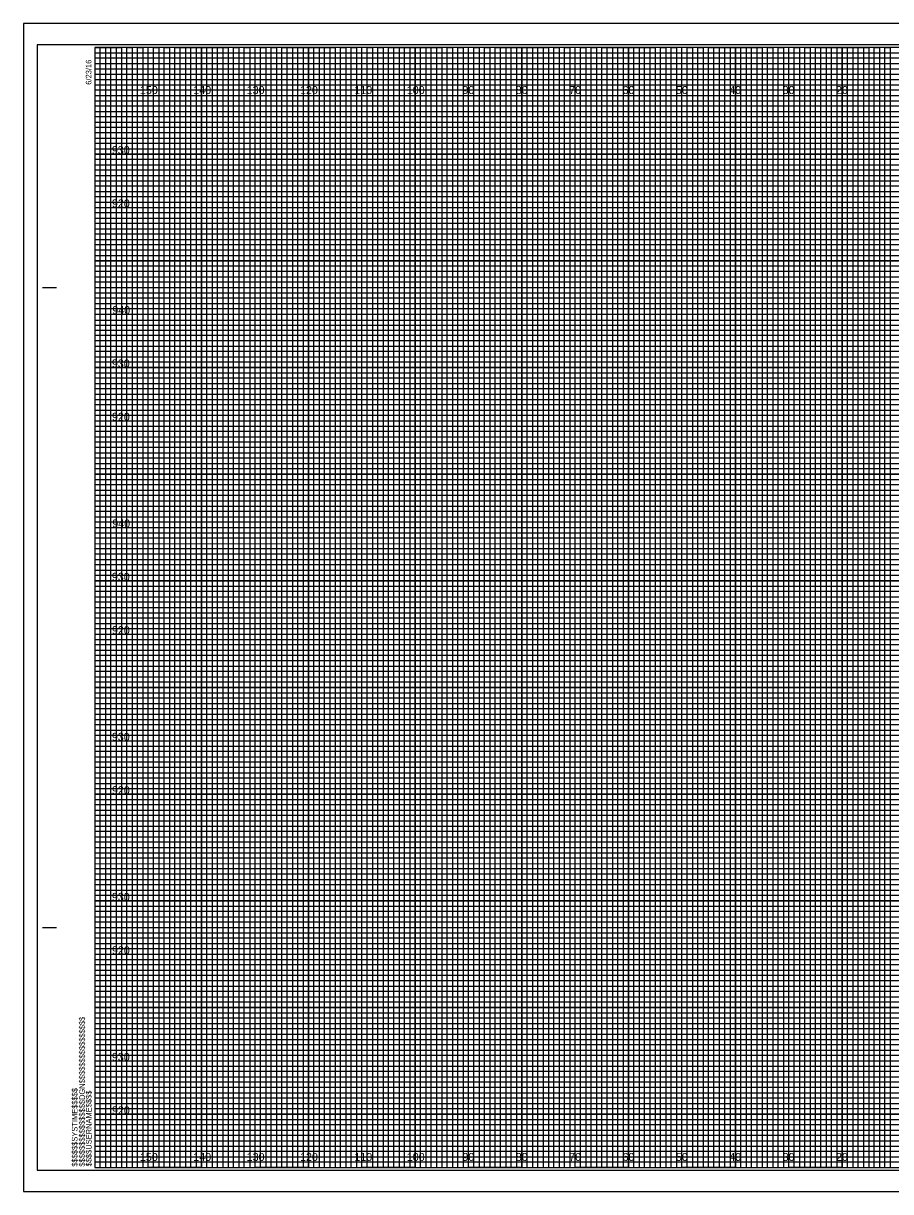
# Model space of a CAD drawing. Extents: x -13 to 323, y 216 to 434.
# Drawn here: x -13.4 to 149.1, y 215.5 to 434.5 of the extents above; entities that cross this region are included whole.
import ezdxf

# ---------------------------------------------------------------- set-up
doc = ezdxf.new("R2010")
doc.units = 0
for name, color, linetype in [('Prop XS Elevation Labels', 7, 'Continuous'), ('Prop XS Label Text', 7, 'Continuous'), ('Prop XS Shear Point Element', 7, 'Continuous'), ('Prop XS Shear Point Label', 7, 'Continuous'), ('Scratch_Level_1', 7, 'Continuous'), ('Scratch_Level_4', 7, 'Continuous'), ('Sheet Cross Section Grid Minor 2 CELL', 7, 'Continuous'), ('Sheet Cutting Line CELL', 7, 'Continuous'), ('Sheet DOT Grid CELL', 7, 'Continuous'), ('Sheet Plot Border Inside CELL', 7, 'Continuous'), ('Sheet Plot Border Outside CELL', 7, 'Continuous')]:
    doc.layers.add(name, color=color, linetype=linetype)

msp = doc.modelspace()

# ---------------------------------------------------------------- linework, layer by layer
at = {"layer": 'Prop XS Label Text'}
for points in [[(0, 430), (5, 430), (5, 220), (15, 220), (15, 430), (25, 430), (25, 220), (35, 220), (35, 430), (45, 430), (45, 220), (55, 220), (55, 430), (65, 430), (65, 220), (75, 220), (75, 430), (85, 430), (85, 220), (95, 220), (95, 430), (105, 430), (105, 220), (115, 220), (115, 430), (125, 430), (125, 220), (135, 220), (135, 430), (145, 430), (145, 220), (155, 220)], [(0, 425), (275, 425)], [(0, 405), (320, 405), (320, 415), (0, 415)], [(0, 385), (320, 385), (320, 395), (0, 395)], [(0, 365), (320, 365), (320, 375), (0, 375)], [(0, 345), (320, 345), (320, 355), (0, 355)], [(0, 325), (320, 325), (320, 335), (0, 335)], [(0, 305), (320, 305), (320, 315), (0, 315)], [(0, 285), (320, 285), (320, 295), (0, 295)], [(0, 265), (320, 265), (320, 275), (0, 275)], [(0, 245), (320, 245), (320, 255), (0, 255)], [(0, 225), (320, 225), (320, 235), (0, 235)]]:
    msp.add_lwpolyline(points, dxfattribs=at)
at = {"layer": 'Prop XS Shear Point Element'}
for p, q in [((-9.8, 385), (-7.3, 385)), ((-9.7, 385), (-7.2, 385)), ((-9.8, 265), (-7.3, 265)), ((-9.7, 265), (-7.2, 265)), ((0, 220), (0, 220)), ((0, 220), (0, 220)), ((0, 220), (0, 220)), ((0, 220), (0, 220)), ((0, 220), (0, 220)), ((0, 220), (0, 220)), ((0, 220), (0, 220))]:
    msp.add_line(p, q, dxfattribs=at)
msp.add_lwpolyline([(320, 430), (0, 430), (0, 220), (320, 220)], close=True, dxfattribs=at)
at = {"layer": 'Prop XS Shear Point Label'}
for p, q in [((0, 429), (260, 429)), ((260, 427.98), (0, 427.98)), ((0, 427.98), (0, 427)), ((0, 427), (260, 427)), ((260, 425.89), (0, 425.89)), ((0, 425.89), (0, 424)), ((0, 424), (320, 424))]:
    msp.add_line(p, q, dxfattribs=at)
for points in [[(0, 423), (270, 423), (320, 423), (320, 422), (0, 422)], [(0, 421), (320, 421), (320, 419), (0, 419)], [(0, 418), (320, 418), (320, 417), (0, 416.98)], [(0, 416), (320, 416), (320, 414), (0, 414)], [(0, 413), (320, 413), (320, 412), (0, 412)], [(0, 411), (320, 411), (320, 409), (0, 409)], [(0, 408), (320, 408), (320, 407), (0, 407)], [(0, 406), (320, 406), (320, 404), (0, 404)], [(0, 403), (320, 403), (320, 402), (0, 402)], [(0, 401), (320, 401), (320, 399), (0, 399)], [(0, 398), (320, 398), (320, 397), (0, 397)], [(0, 396), (320, 396), (320, 393.95), (320, 393), (320, 392), (0, 392)], [(0, 394), (320, 394), (320, 393), (0, 393)], [(0, 391), (320, 391), (320, 389), (0, 389.03)], [(0, 389.03), (320, 389), (320, 388), (0, 388)], [(0, 387), (320, 387), (320, 386), (0, 386)], [(0, 384), (320, 384), (320, 383), (0, 383)], [(0, 382), (320, 382), (320, 381), (0, 381)], [(-0.07, 378.89), (320, 378.89), (320, 377.88), (-0.07, 377.88)], [(0, 377), (320, 377), (320, 376), (0, 376)], [(0, 374), (320, 374), (320, 373), (0, 373)], [(0, 372), (320, 372), (320, 371), (0, 371)], [(0, 369), (320, 369), (320, 368), (0, 368)], [(0, 367), (320, 367), (320, 366), (0, 366)], [(0, 364), (320, 364), (320, 363), (0, 363)], [(0, 362), (320, 362), (320, 361), (0, 361)], [(0, 359), (320, 359), (319.99, 357.98), (0, 358)], [(0, 357), (320, 357), (320, 356), (0, 356)], [(0, 354), (320, 354), (320, 353), (0, 353)], [(0, 352), (320, 352), (320, 351), (0, 351)], [(0, 349), (320, 349), (320, 348), (0, 348)], [(0, 347), (320, 347), (320, 346), (0, 346)], [(0, 344), (320, 344), (320, 343), (0, 343)], [(0, 342), (320, 342), (320, 341), (0, 341)], [(0, 339), (320, 339), (320, 338), (0, 338)], [(0, 336.99), (320.07, 336.91), (320, 336), (0, 336)], [(0, 334), (320, 334), (320, 333), (0, 333)], [(0, 332), (320, 332), (320, 331), (0, 331)], [(0, 329), (320, 329), (320, 328), (0, 328)], [(0, 327), (320, 327), (320, 326), (0, 326)], [(0, 324), (320, 324), (320, 323), (0, 323)], [(0, 322), (320, 322), (320, 321), (0, 321)], [(0, 319), (320, 319), (320, 318), (0, 318)], [(0, 317), (320, 317), (320, 316), (0, 316)], [(0, 314), (320, 314), (320, 313), (0, 313)], [(0, 312), (320, 312), (320, 311), (0, 311)], [(0, 309), (320, 309), (320, 308), (0, 308)], [(0, 307), (320, 307), (320, 306), (0, 306)], [(0, 304), (320, 304), (320, 303), (0, 303)], [(0, 302), (320, 302), (320, 301), (0, 301)], [(0, 299), (320, 299), (319.99, 297.98), (0, 298)], [(0, 297), (320, 297), (320, 296), (0, 296)], [(0, 294), (320, 294), (320, 293), (0, 293)], [(0, 292), (320, 292), (320, 291), (0, 291)], [(0, 289), (320, 289), (320, 288), (0, 288)], [(0, 287), (320, 287), (320, 286), (0, 286)], [(0, 284), (320, 284), (320, 283), (0, 283)], [(0, 282), (320, 282), (320, 281), (0, 281)], [(0, 279), (320, 279), (320, 278), (0, 278)], [(0, 276.99), (320.07, 276.91), (320, 276), (0, 276)], [(0, 274), (320, 274), (320, 273), (0, 273)], [(0, 272), (320, 272), (320, 271), (0, 271)], [(0, 269), (320, 269), (320, 268), (0, 268)], [(0, 267), (320, 267), (320, 266), (0, 266)], [(0, 264), (320, 264), (320, 263), (0, 263)], [(0, 262), (320, 262), (320, 261), (0, 261)], [(0, 259), (320, 259), (320, 258), (0, 258)], [(0, 257), (320, 257), (320, 256), (0, 256)], [(0, 254), (320, 254), (320, 253), (0, 253)], [(0, 252), (320, 252), (320, 251), (0, 251)], [(0, 249), (320, 249), (320, 248), (0, 248)], [(0, 247), (320, 247), (320, 246), (0, 246)], [(0, 244), (320, 244), (320, 243), (0, 243)], [(0, 242), (320, 242), (320, 241), (0, 241)], [(0, 239), (320, 239), (320, 238), (0, 238)], [(0, 237), (320, 237), (320, 236), (0, 236)], [(0, 234), (320, 234), (320, 233), (0, 233)], [(0, 232), (320, 232), (320, 231), (0, 231)], [(0, 229), (320, 229), (320, 228), (0, 228)], [(0, 227), (320, 227), (320, 226), (0, 226)], [(0, 224), (320, 224), (320, 223), (0, 223)], [(0, 222), (320, 222), (320, 221), (0, 221)]]:
    msp.add_lwpolyline(points, dxfattribs=at)
at = {"layer": 'Scratch_Level_4'}
for p, q in [((10, 430), (0, 430)), ((10, 220), (10, 430)), ((30, 430), (20, 430)), ((20, 430), (20, 220)), ((30, 220), (30, 430)), ((50, 430), (40, 430)), ((40, 430), (40, 220)), ((50, 220), (50, 430)), ((70, 430), (60, 430)), ((60, 430), (60, 220)), ((70, 220), (70, 430)), ((90, 430), (80, 430)), ((80, 430), (80, 220)), ((90, 220), (90, 430)), ((110, 430), (100, 430)), ((100, 430), (100, 220)), ((110, 220), (110, 430)), ((130, 430), (120, 430)), ((120, 430), (120, 220)), ((130, 220), (130, 430)), ((150, 430), (140, 430)), ((140, 430), (140, 220)), ((20, 220), (10, 220)), ((40, 220), (30, 220)), ((60, 220), (50, 220)), ((80, 220), (70, 220)), ((100, 220), (90, 220)), ((120, 220), (110, 220)), ((140, 220), (130, 220))]:
    msp.add_line(p, q, dxfattribs=at)
for points in [[(0, 420), (320, 420), (320, 410), (0, 410)], [(0, 400), (320, 400), (320, 390), (0, 390)], [(0, 380), (320, 380), (320, 370), (0, 370)], [(0, 360), (320, 360), (320, 350), (0, 350)], [(0, 340), (320, 340), (320, 330), (0, 330)], [(0, 320), (320, 320), (320, 310), (0, 310)], [(0, 300), (320, 300), (320, 290), (0, 290)], [(0, 280), (320, 280), (320, 270), (0, 270)], [(0, 260), (320, 260), (320, 250), (0, 250)], [(0, 240), (320, 240), (320, 230), (0, 230)]]:
    msp.add_lwpolyline(points, dxfattribs=at)
at = {"layer": 'Sheet Cross Section Grid Minor 2 CELL'}
for points in [[(0, 220), (1, 220), (1, 430), (2, 430), (2, 220)], [(2, 220), (3, 220), (3, 430), (4, 430), (4, 220)], [(5, 220), (6, 220), (6, 430), (7, 430), (7, 220)], [(7, 220), (8, 220), (8, 430), (9, 430), (9, 220)], [(10, 220), (11, 220), (11, 430), (12, 430), (12, 220)], [(12, 220), (13, 220), (13, 430), (14, 430), (14, 220)], [(15, 220), (16, 220), (16, 430), (17, 430), (17, 220)], [(17, 220), (18, 220), (18, 430), (19, 430), (19, 220)], [(20, 220), (21, 220), (21, 430), (22, 430), (22, 220)], [(22, 220), (23, 220), (23, 430), (24, 430), (24, 220)], [(25, 220), (26, 220), (26, 430), (27, 430), (27, 220)], [(27, 220), (28, 220), (28, 430), (29, 430), (29, 220)], [(30, 220), (31, 220), (31, 430), (32, 430), (32, 220)], [(32, 220), (33, 220), (33, 430), (34, 430), (34, 220)], [(35, 220), (36, 220), (36, 430), (37, 430), (37, 220)], [(37, 220), (38, 220), (38, 430), (39, 430), (39, 220)], [(40, 220), (41, 220), (41, 430), (42, 430), (42, 220)], [(42, 220), (43, 220), (43, 430), (44, 430), (44, 220)], [(45, 220), (46, 220), (46, 430), (47, 430), (47, 220)], [(47, 220), (48, 220), (48, 430), (49, 430), (49, 220)], [(50, 220), (51, 220), (51, 430), (52, 430), (52, 220)], [(52, 220), (53, 220), (53, 430), (54, 430), (54, 220)], [(55, 220), (56, 220), (56, 430), (57, 430), (57, 220)], [(57, 220), (58, 220), (58, 430), (59, 430), (59, 220)], [(60, 220), (61, 220), (61, 430), (62, 430), (62, 220)], [(62, 220), (63, 220), (63, 430), (64, 430), (64, 220)], [(65, 220), (66, 220), (66, 430), (67, 430), (67, 220)], [(67, 220), (68, 220), (68, 430), (69, 430), (69, 220)], [(70, 220), (71, 220), (71, 430), (72, 430), (72, 220)], [(72, 220), (73, 220), (73, 430), (74, 430), (74, 220)], [(75, 220), (76, 220), (76, 430), (77, 430), (77, 220)], [(77, 220), (78, 220), (78, 430), (79, 430), (79, 220)], [(80, 220), (81, 220), (81, 430), (82, 430), (82, 220)], [(82, 220), (83, 220), (83, 430), (84, 430), (84, 220)], [(85, 220), (86, 220), (86, 430), (87, 430), (87, 220)], [(87, 220), (88, 220), (88, 430), (89, 430), (89, 220)], [(90, 220), (91, 220), (91, 430), (92, 430), (92, 220)], [(92, 220), (93, 220), (93, 430), (94, 430), (94, 220)], [(95, 220), (96, 220), (96, 430), (97, 430), (97, 220)], [(97, 220), (98, 220), (98, 430), (99, 430), (99, 220)], [(100, 220), (101, 220), (101, 430), (102, 430), (102, 220)], [(102, 220), (103, 220), (103, 430), (104, 430), (104, 220)], [(105, 220), (106, 220), (106, 430), (107, 430), (107, 220)], [(107, 220), (108, 220), (108, 430), (109, 430), (109, 220)], [(110, 220), (111, 220), (111, 430), (112, 430), (112, 220)], [(112, 220), (113, 220), (113, 430), (114, 430), (114, 220)], [(115, 220), (116, 220), (116, 430), (117, 430), (117, 220)], [(117, 220), (118, 220), (118, 430), (119, 430), (119, 220)], [(120, 220), (121, 220), (121, 430), (122, 430), (122, 220)], [(122, 220), (123, 220), (123, 430), (124, 430), (124, 220)], [(125, 220), (126, 220), (126, 430), (127, 430), (127, 220)], [(127, 220), (128, 220), (128, 430), (129, 430), (129, 220)], [(130, 220), (131, 220), (131, 430), (132, 430), (132, 220)], [(132, 220), (133, 220), (133, 430), (134, 430), (134, 220)], [(135, 220), (136, 220), (136, 430), (137, 430), (137, 220)], [(137, 220), (138, 220), (138, 430), (139, 430), (139, 220)], [(140, 220), (141, 220), (141, 430), (142, 430), (142, 220)], [(142, 220), (143, 220), (143, 430), (144, 430), (144, 220)], [(145, 220), (146, 220), (146, 430), (147, 430), (147, 220)], [(147, 220), (148, 220), (148, 430), (149, 430), (149, 220)]]:
    msp.add_lwpolyline(points, dxfattribs=at)
at = {"layer": 'Sheet Cutting Line CELL'}
for p, q in [((323.3, 434.5), (-13.4, 434.5)), ((-13.4, 434.5), (-13.4, 215.5)), ((-13.4, 215.5), (323.3, 215.5))]:
    msp.add_line(p, q, dxfattribs=at)
at = {"layer": 'Sheet DOT Grid CELL'}
for p, q in [((10, 220), (10, 430)), ((20, 220), (20, 430)), ((30, 220), (30, 430)), ((40, 220), (40, 430)), ((50, 220), (50, 430)), ((60, 220), (60, 430)), ((70, 220), (70, 430)), ((80, 220), (80, 430)), ((90, 220), (90, 430)), ((100, 220), (100, 430)), ((110, 220), (110, 430)), ((120, 220), (120, 430)), ((130, 220), (130, 430)), ((140, 220), (140, 430)), ((0, 420), (320, 420)), ((0, 410), (320, 410)), ((0, 400), (320, 400)), ((0, 390), (320, 390)), ((0, 380), (320, 380)), ((0, 370), (320, 370)), ((0, 360), (320, 360)), ((0, 350), (320, 350)), ((0, 340), (320, 340)), ((0, 330), (320, 330)), ((0, 320), (320, 320)), ((0, 310), (320, 310)), ((0, 300), (320, 300)), ((0, 290), (320, 290)), ((0, 280), (320, 280)), ((0, 270), (320, 270)), ((0, 260), (320, 260)), ((0, 250), (320, 250)), ((0, 240), (320, 240)), ((0, 230), (320, 230))]:
    msp.add_line(p, q, dxfattribs=at)
at = {"layer": 'Sheet Plot Border Inside CELL'}
msp.add_lwpolyline([(-10.8, 219.5), (322.4, 219.5), (322.4, 430.5), (-10.8, 430.5)], close=True, dxfattribs=at)
at = {"layer": 'Sheet Plot Border Outside CELL'}
msp.add_lwpolyline([(-13.4, 215.5), (323.3, 215.5), (323.3, 434.5), (-13.4, 434.5)], close=True, dxfattribs=at)

# ---------------------------------------------------------------- texts
at = {"layer": 'Prop XS Elevation Labels'}
for s, p in [('930', (3.18, 410)), ('920', (3.19, 400)), ('940', (3.26, 380)), ('930', (3.18, 370)), ('920', (3.19, 360)), ('940', (3.26, 340)), ('930', (3.18, 330)), ('920', (3.19, 320)), ('930', (3.18, 300)), ('920', (3.19, 290)), ('930', (3.18, 270)), ('920', (3.19, 260)), ('930', (3.18, 240)), ('920', (3.19, 230))]:
    msp.add_text(s, height=1.5, dxfattribs=at).set_placement(p)
at = {"layer": 'Prop XS Shear Point Element'}
for s, p in [('6/23/16', (-0.65, 423)), ('$$$$$$$$$$$$$$$$DGN$$$$$$$$$$$$$$$$', (-1.88, 220.18)), ('$$$$$$SYSTIME$$$$$', (-3.26, 220.18)), ('$$$$USERNAME$$$$', (-0.62, 220.23))]:
    msp.add_text(s, height=1.05, rotation=90, dxfattribs=at).set_placement(p)
at = {"layer": 'Scratch_Level_1'}
for s, p in [('150', (8.44, 421.25)), ('140', (18.44, 421.25)), ('130', (28.44, 421.25)), ('120', (38.44, 421.25)), ('110', (48.62, 421.25)), ('100', (58.44, 421.25)), ('90', (68.86, 421.25)), ('80', (78.86, 421.25)), ('70', (88.86, 421.25)), ('60', (98.86, 421.25)), ('50', (108.86, 421.25)), ('40', (118.86, 421.25)), ('30', (128.86, 421.25)), ('20', (138.86, 421.25)), ('150', (8.44, 221.25)), ('140', (18.44, 221.25)), ('130', (28.44, 221.25)), ('120', (38.44, 221.25)), ('110', (48.62, 221.25)), ('100', (58.44, 221.25)), ('90', (68.86, 221.25)), ('80', (78.86, 221.25)), ('70', (88.86, 221.25)), ('60', (98.86, 221.25)), ('50', (108.86, 221.25)), ('40', (118.86, 221.25)), ('30', (128.86, 221.25)), ('20', (138.86, 221.25))]:
    msp.add_text(s, height=1.5, dxfattribs=at).set_placement(p)

doc.saveas('drawing.dxf')
